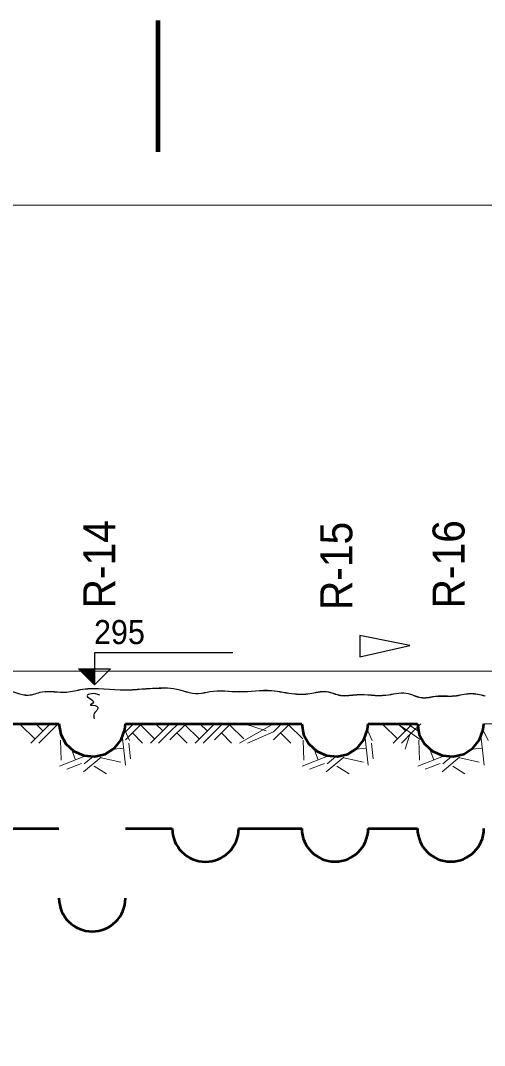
# Model space of a CAD drawing. Extents: x 8458 to 9360, y 19921 to 20366.
# Drawn here: x 8970.9 to 9028.9, y 20113.5 to 20241.4 of the extents above; entities that cross this region are included whole.
import ezdxf

# ---------------------------------------------------------------- set-up
doc = ezdxf.new("R2010")
doc.units = 0
doc.header["$LTSCALE"] = 1.2
doc.layers.add('5', color=7, linetype='Continuous', lineweight=13)

msp = doc.modelspace()

# ---------------------------------------------------------------- linework, layer by layer
at = {"layer": '5', "lineweight": 90}
msp.add_line((8988.14, 20225.05), (8988.14, 20241.43), dxfattribs=at)
at = {"layer": '5'}
for p, q in [((8509.89, 20218.4), (9341.84, 20218.4)), ((8509.89, 20160.27), (9341.84, 20160.27)), ((8970.95, 20153.56), (8972.72, 20151.79)), ((8974.63, 20153.7), (8972.21, 20151.28)), ((8972.83, 20153.7), (8973.73, 20152.8)), ((8974.63, 20152.69), (8973.22, 20151.28)), ((8975.64, 20153.7), (8974.63, 20152.69)), ((8983.94, 20152.91), (8984.55, 20151.62)), ((8985.04, 20153.7), (8984.03, 20152.69)), ((8985.04, 20153.7), (8984.03, 20152.69)), ((8986.05, 20153.7), (8984.03, 20151.68)), ((8985.91, 20153.56), (8987.68, 20151.79)), ((8989.59, 20153.7), (8987.17, 20151.28)), ((8987.79, 20153.7), (8988.69, 20152.8)), ((8989.59, 20152.69), (8988.18, 20151.28)), ((8990.6, 20153.7), (8989.59, 20152.69)), ((8991.6, 20153.7), (8989.59, 20151.68)), ((8991.47, 20153.56), (8993.24, 20151.79)), ((8995.15, 20153.7), (8992.73, 20151.28)), ((8993.34, 20153.7), (8994.25, 20152.8)), ((8995.15, 20152.69), (8993.74, 20151.28)), ((8996.16, 20153.7), (8995.15, 20152.69)), ((8997.16, 20153.7), (8995.15, 20151.68)), ((8997.03, 20153.56), (8998.8, 20151.79)), ((9002.53, 20153.7), (8998.29, 20151.28)), ((8998.9, 20153.7), (9001.62, 20152.8)), ((9002.53, 20152.69), (8999.29, 20151.28)), ((9003.53, 20153.7), (9002.53, 20152.69)), ((9004.54, 20153.7), (9002.53, 20151.68)), ((9004.4, 20153.56), (9006.18, 20151.79)), ((9014.24, 20152.91), (9014.85, 20151.62)), ((9016.21, 20153.56), (9017.98, 20151.79)), ((9019.89, 20153.7), (9017.47, 20151.28)), ((9018.09, 20153.7), (9018.99, 20152.8)), ((9019.89, 20152.69), (9018.48, 20151.28)), ((9020.83, 20151.71), (9018.5, 20153.36)), ((9020.66, 20152.71), (9019.5, 20153.53)), ((9020.9, 20153.7), (9019.89, 20152.69)), ((9028.69, 20152.91), (9029.3, 20151.62)), ((8975.91, 20151.64), (8976.01, 20149.13)), ((8983.68, 20151.91), (8984.05, 20148.51)), ((8984.9, 20152.55), (8986.17, 20151.28)), ((8990.46, 20152.55), (8991.73, 20151.28)), ((8996.02, 20152.55), (8997.29, 20151.28)), ((9003.4, 20152.55), (9004.67, 20151.28)), ((9006.21, 20151.64), (9006.31, 20149.13)), ((9013.98, 20151.91), (9014.35, 20148.51)), ((9019.48, 20152.24), (9018.97, 20150.52)), ((9020.66, 20151.64), (9020.76, 20149.13)), ((9028.43, 20151.91), (9028.8, 20148.51)), ((8977.33, 20150.38), (8977.79, 20149.19)), ((8982.55, 20150.51), (8983.82, 20150.65)), ((8984.47, 20151.28), (8984.68, 20149.3)), ((9007.63, 20150.38), (9008.09, 20149.19)), ((9012.85, 20150.51), (9014.12, 20150.65)), ((9014.77, 20151.28), (9014.98, 20149.3)), ((9022.08, 20150.38), (9022.54, 20149.19)), ((9027.3, 20150.51), (9028.57, 20150.65)), ((8978.98, 20149.65), (8975.79, 20148.42)), ((8981, 20149.52), (8978.81, 20147.69)), ((8979.99, 20149.61), (8978.9, 20148.69)), ((8981.01, 20149.42), (8983.45, 20148.88)), ((9009.28, 20149.65), (9006.09, 20148.42)), ((9011.3, 20149.52), (9009.11, 20147.69)), ((9010.29, 20149.61), (9009.2, 20148.69)), ((9011.31, 20149.42), (9013.75, 20148.88)), ((9023.73, 20149.65), (9020.54, 20148.42)), ((9025.75, 20149.52), (9023.56, 20147.69)), ((9024.74, 20149.61), (9023.65, 20148.69)), ((9025.76, 20149.42), (9028.2, 20148.88)), ((8978.57, 20148.73), (8976.71, 20148.01)), ((8980.14, 20148.4), (8981.67, 20147.46)), ((9008.87, 20148.73), (9007.01, 20148.01)), ((9010.44, 20148.4), (9011.97, 20147.46)), ((9023.32, 20148.73), (9021.46, 20148.01)), ((9024.89, 20148.4), (9026.42, 20147.46))]:
    msp.add_line(p, q, dxfattribs=at)
at = {"layer": '5', "lineweight": 53}
for p, q in [((8969.07, 20153.7), (8975.74, 20153.7)), ((8984.03, 20153.7), (9006.04, 20153.7)), ((8984.03, 20153.7), (9006.04, 20153.7)), ((9014.33, 20153.7), (9020.49, 20153.7)), ((8969.07, 20140.61), (8975.74, 20140.61)), ((8984.03, 20140.61), (8989.88, 20140.61)), ((8998.17, 20140.61), (9006.04, 20140.61)), ((9014.33, 20140.61), (9020.49, 20140.61))]:
    msp.add_line(p, q, dxfattribs=at)
at = {"layer": '5', "lineweight": 25}
msp.add_lwpolyline([(9019.52, 20163.47), (9013.3, 20164.69), (9013.3, 20162.05)], close=True, dxfattribs=at)
msp.add_lwpolyline([(8997.44, 20162.54), (8980.19, 20162.54), (8980.19, 20158.54), (8978.19, 20160.54), (8982.19, 20160.54), (8980.19, 20158.54)], dxfattribs=at)
at = {"layer": '5', "lineweight": 35}
for points in [[(8980.14, 20158.65), (8978.47, 20160.42), (8980.05, 20160.41), (8980.09, 20158.84), (8978.78, 20160.26), (8979.93, 20160.27), (8979.97, 20159.15), (8979.11, 20160.13), (8979.8, 20160.14), (8979.88, 20159.41), (8979.48, 20160.02)], [(8979.8, 20159.73), (8979.69, 20160.07), (8979.27, 20160.06), (8979.88, 20159.36)]]:
    msp.add_lwpolyline(points, dxfattribs=at)
at = {"layer": '5'}
for points in [[(8954.99, 20153.7), (8955.15, 20151.94), (8955.75, 20150.28), (8956.74, 20148.82), (8958.07, 20147.65), (8959.64, 20146.85), (8961.37, 20146.46), (8963.13, 20146.52), (8964.83, 20147.01), (8966.35, 20147.91), (8967.6, 20149.16), (8968.49, 20150.68), (8968.99, 20152.37), (8969.1, 20153.7), (8975.74, 20153.7)], [(8975.74, 20153.7), (8975.97, 20152.37), (8976.61, 20151.18), (8977.61, 20150.26), (8978.85, 20149.71), (8980.19, 20149.59), (8981.51, 20149.91), (8982.65, 20150.63), (8983.5, 20151.69), (8983.96, 20152.96), (8984.03, 20153.7), (9006.04, 20153.7)], [(9006.04, 20153.7), (9006.27, 20152.37), (9006.91, 20151.18), (9007.91, 20150.26), (9009.15, 20149.71), (9010.49, 20149.59), (9011.81, 20149.91), (9012.95, 20150.63), (9013.8, 20151.69), (9014.26, 20152.96), (9014.33, 20153.7), (9020.49, 20153.7)], [(9020.49, 20153.7), (9020.72, 20152.37), (9021.36, 20151.18), (9022.36, 20150.26), (9023.6, 20149.71), (9024.94, 20149.59), (9026.26, 20149.91), (9027.4, 20150.63), (9028.25, 20151.69), (9028.71, 20152.96), (9028.78, 20153.67), (9046.04, 20153.67), (9046.04, 20113.55)]]:
    msp.add_lwpolyline(points, dxfattribs=at)
at = {"layer": '5', "lineweight": 53}
for points in [[(8975.74, 20153.7), (8975.97, 20152.37), (8976.61, 20151.18), (8977.61, 20150.26), (8978.85, 20149.71), (8980.19, 20149.59), (8981.51, 20149.91), (8982.65, 20150.63), (8983.5, 20151.69), (8983.96, 20152.96), (8984.03, 20153.7)], [(9006.04, 20153.7), (9006.27, 20152.37), (9006.91, 20151.18), (9007.91, 20150.26), (9009.15, 20149.71), (9010.49, 20149.59), (9011.81, 20149.91), (9012.95, 20150.63), (9013.8, 20151.69), (9014.26, 20152.96), (9014.33, 20153.7)], [(9020.49, 20153.7), (9020.72, 20152.37), (9021.36, 20151.18), (9022.36, 20150.26), (9023.6, 20149.71), (9024.94, 20149.59), (9026.26, 20149.91), (9027.4, 20150.63), (9028.25, 20151.69), (9028.71, 20152.96), (9028.78, 20153.7)]]:
    msp.add_lwpolyline(points, dxfattribs=at)
for centre in [(8994.03, 20140.63), (9010.19, 20140.64), (9024.64, 20140.64), (8979.89, 20131.94)]:
    msp.add_arc(centre, 4.15, 180.3534, 359.6466, dxfattribs=at)
at = {"layer": '5', "lineweight": 25}
for points in [[(8956.89, 20157.33), (8958.82, 20157.22), (8962.9, 20157.61), (8965.39, 20157.39), (8968.95, 20157.94), (8971.9, 20157.26), (8973.63, 20157.66), (8976.68, 20157.64), (8978.67, 20157.99), (8984.06, 20157.91), (8986.35, 20158.05), (8988.49, 20158.15), (8990.06, 20158.09), (8993.16, 20157.46), (8994.59, 20157.71), (8998.25, 20157.69), (9002.26, 20157.83), (9005.16, 20157.41), (9007.04, 20157.45), (9009.13, 20157.7), (9010.9, 20157.23), (9012.94, 20157.32), (9016.55, 20157.25), (9019.09, 20157.5), (9021.13, 20156.93), (9022.75, 20157.12), (9025.1, 20157.16), (9027.08, 20157.46), (9028.92, 20157.17)], [(8980.82, 20157.24), (8979.74, 20157.44), (8979.24, 20157.18), (8979.9, 20156.62), (8980.04, 20156.38), (8979.64, 20156.06), (8980.5, 20155.86), (8980.56, 20155.5), (8980.14, 20154.96), (8980.14, 20154.3)]]:
    msp.add_spline(points, degree=3, dxfattribs=at)
at = {"layer": '5'}
msp.add_spline([(9028.93, 20157.18), (9027.09, 20157.48), (9025.11, 20157.18), (9022.76, 20157.14), (9021.14, 20156.95), (9019.1, 20157.52), (9016.56, 20157.27), (9012.95, 20157.34), (9010.91, 20157.25), (9009.14, 20157.72), (9007.05, 20157.47), (9005.17, 20157.43), (9002.27, 20157.85), (8998.26, 20157.7), (8994.6, 20157.72), (8993.17, 20157.47), (8990.07, 20158.1), (8988.5, 20158.16), (8986.36, 20158.06), (8984.07, 20157.92), (8978.68, 20158), (8976.69, 20157.65), (8973.64, 20157.67), (8971.91, 20157.27), (8968.96, 20157.95), (8965.4, 20157.4), (8962.91, 20157.62), (8958.83, 20157.23), (8956.9, 20157.34)], degree=3, dxfattribs=at)

# ---------------------------------------------------------------- texts
at = {"layer": '5', "width": 0.95}
for s, p in [('R-14', (8982.77, 20168.08)), ('R-15', (9012.36, 20167.87)), ('R-16', (9026.37, 20168.08))]:
    msp.add_text(s, height=4, rotation=90, dxfattribs=at).set_placement(p)
msp.add_text('295', height=3, dxfattribs=at).set_placement((8980.11, 20163.63))

doc.saveas('drawing.dxf')
